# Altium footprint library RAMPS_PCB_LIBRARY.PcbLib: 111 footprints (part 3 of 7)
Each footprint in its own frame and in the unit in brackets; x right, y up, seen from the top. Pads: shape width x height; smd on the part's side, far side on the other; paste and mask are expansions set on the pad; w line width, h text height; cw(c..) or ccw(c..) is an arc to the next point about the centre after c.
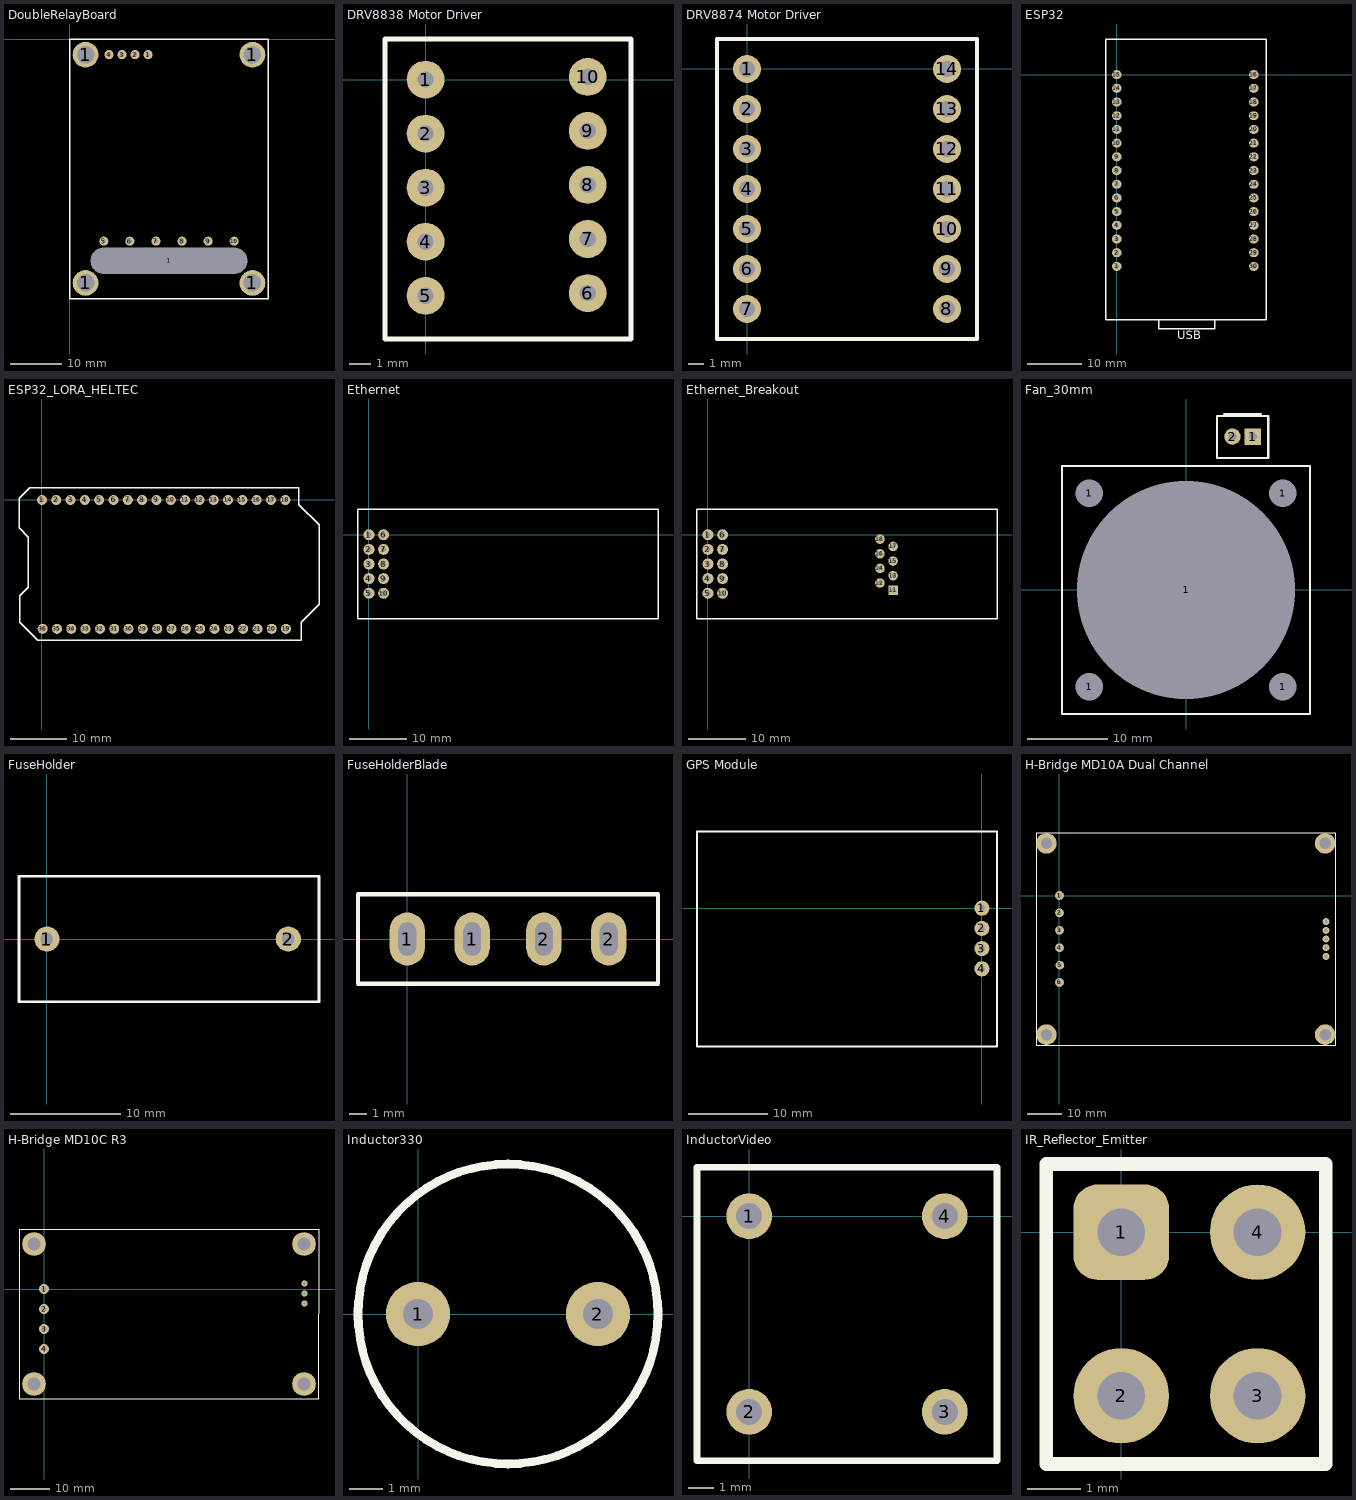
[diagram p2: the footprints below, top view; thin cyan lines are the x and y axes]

## DoubleRelayBoard [mil]
pads (15):
  round 196.85 hole 133.86: 1(120,-1870) 1(120,-120) 1(1400,-1870) 1(1400,-120)
  round 70 hole 30: 1(600,-120) 2(500,-120) 3(400,-120) 4(300,-120) 5(260,-1550) 6(460,-1550) 7(660,-1550) 8(860,-1550) 9(1060,-1550) 10(1260,-1550)
  rect 60x60 hole 200 slot 1200 at 0 deg: 1(760,-1700)
Top Overlay:
  lines w10: 0,-1990 1520,-1990 1520,0 0,0 0,-1990

## DRV8838 Motor Driver [mil]
pads (10):
  round 70 hole 30: 1(0,0) 2(0,-100) 3(0,-200) 4(0,-300) 5(0,-400) 6(300,-395) 7(300,-295) 8(300,-195) 9(300,-95) 10(300,5)
Top Overlay:
  lines w10: -75,-480 -75,75 380,75 380,-480 -75,-480

## DRV8874 Motor Driver [mil]
pads (14):
  round 70 hole 40: 1(0,0) 2(0,-100) 3(0,-200) 4(0,-300) 5(0,-400) 6(0,-500) 7(0,-600) 8(500,-600) 9(500,-500) 10(500,-400) 11(500,-300) 12(500,-200) 13(500,-100) 14(500,0)
Top Overlay:
  lines w10: -75,-675 -75,75 575,75 575,-675 -75,-675

## ESP32 [mil]
pads (30):
  oval 70x65 hole 35: 1(0,-1400) 2(0,-1300) 3(0,-1200) 4(0,-1100) 5(0,-1000) 6(0,-900) 7(0,-800) 8(0,-700) 9(0,-600) 10(0,-500) 11(0,-400) 12(0,-300) 13(0,-200) 14(0,-100) 15(0,0) 16(1000,0) 17(1000,-100) 18(1000,-200) 19(1000,-300) 20(1000,-400) 21(1000,-500) 22(1000,-600) 23(1000,-700) 24(1000,-800) 25(1000,-900) 26(1000,-1000) 27(1000,-1100) 28(1000,-1200) 29(1000,-1300) 30(1000,-1400)
Top Overlay:
  lines w10: 305,-1795 305,-1855 715,-1855 715,-1790 ; -80,-1790 1090,-1790 1090,260 -80,260 -80,-1790
  text "USB" at 440,-1930 h60

## ESP32_LORA_HELTEC [mil]
pads (36):
  round 70 hole 35: 1(0,0) 2(100,0) 3(200,0) 4(300,0) 5(400,0) 6(500,0) 7(600,0) 8(700,0) 9(800,0) 10(900,0) 11(1000,0) 12(1100,0) 13(1200,0) 14(1300,0) 15(1400,0) 16(1500,0) 17(1600,0) 18(1700,0) 19(1705,-900) 20(1605,-900) 21(1505,-900) 22(1405,-900) 23(1305,-900) 24(1205,-900) 25(1105,-900) 26(1005,-900) 27(905,-900) 28(805,-900) 29(705,-900) 30(605,-900) 31(505,-900) 32(405,-900) 33(305,-900) 34(205,-900) 35(105,-900) 36(5,-900)
Top Overlay:
  lines w10: -160,-195 -160,10 -85,85 -75,85 1795,85 1795,-35 1935,-175 1935,-730 1810,-855 1810,-980 -30,-980 -155,-855 -155,-670 -95,-610 -95,-260 -160,-195

## Ethernet [mil]
pads (10):
  round 75 hole 35: 1(0,0) 2(0,-100) 3(0,-200) 4(0,-300) 5(0,-400) 6(100,0) 7(100,-100) 8(100,-200) 9(100,-300) 10(100,-400)
Top Overlay:
  lines w10: -75,-575 -75,175 1975,175 1975,-575 -75,-575

## Ethernet_Breakout [mil]
pads (18):
  round 75 hole 35: 1(0,0) 2(0,-100) 3(0,-200) 4(0,-300) 5(0,-400) 6(100,0) 7(100,-100) 8(100,-200) 9(100,-300) 10(100,-400)
  rect 65x65 hole 30: 11(1265,-380)
  round 65 hole 30: 12(1175,-330) 13(1265,-280) 14(1175,-230) 15(1265,-180) 16(1175,-130) 17(1265,-80) 18(1175,-30)
Top Overlay:
  lines w10: -75,-575 1975,-575 1975,175 -75,175 -75,-575

## Fan_30mm [mil]
pads (7):
  round 60 hole 133.86: 1(-472.44,-472.44) 1(-472.44,472.44) 1(472.44,-472.44) 1(472.44,472.44)
  round 60 hole 1062.99: 1(0,0)
  rect 80x80 hole 40: 1(326.23,748.05)
  round 80 hole 40: 2(226.23,748.05)
Top Overlay:
  lines w10: 186.23,858.05 366.23,858.05 ; -605,-605 605,-605 605,605 -605,605 -605,-605 ; 151.23,643.05 151.23,848.05 401.23,848.05 401.23,643.05 151.23,643.05

## FuseHolder [mil]
pads (2):
  round 90 hole 45: 1(0,0) 2(865,0)
Top Overlay:
  lines w10: -100,-225 -100,225 975,225 975,-225 -100,-225

## FuseHolderBlade [mm]
pads (4):
  oval 2x3 hole 1 slot 1.9 at 90 deg: 1(0,0) 1(3.683,0) 2(7.747,0) 2(11.43,0)
Top Overlay:
  lines w0.254: -2.794,-2.54 -2.794,2.54 14.224,2.54 14.224,-2.54 -2.794,-2.54

## GPS Module [mil]
pads (4):
  round 75 hole 30: 1(0,0) 2(0,-100) 3(0,-200) 4(0,-300)
Top Overlay:
  lines w10: -1410,-685 -1410,380 75,380 75,-685 -1410,-685

## H-Bridge MD10A Dual Channel [mil]
pads (15):
  round 100 hole 50: 1(0,0) 2(0,-200) 3(0,-400) 4(0,-600) 5(5,-800) 6(0,-1000)
  round 80 hole 40: 7(3065,-700) 8(3065,-600) 9(3065,-500) 10(3065,-400) 11(3065,-300)
  round 236.22 hole 129.92: ""(-150,-1600) ""(-150,600) ""(3055,-1600) ""(3055,600)
Top Overlay:
  lines w10: -270,-1720 -270,720 3180,720 3180,-1720 -270,-1720

## H-Bridge MD10C R3 [mil]
pads (11):
  round 100 hole 50: 1(0,0) 2(0,-200) 3(0,-400) 4(0,-600)
  round 60 hole 30: 5(2605,-145) 6(2605,-45) 7(2605,55)
  round 236.22 hole 129.92: ""(-100,-950) ""(-100,450) ""(2600,-950) ""(2600,450)
Top Overlay:
  lines w10: -250,-1100 -250,600 2750,600 2750,-1100 -250,-1100

## Inductor330 [mil]
pads (2):
  round 75 hole 35: 1(0,0) 2(210,0)
Top Overlay:
  circle w10: c105,0 r175.07

## InductorVideo [mil]
pads (4):
  round 70 hole 40: 1(0,0) 2(0,-300) 3(300,-300) 4(300,0)
Top Overlay:
  lines w10: -80,-375 -80,75 380,75 380,-375 -80,-375

## IR_Reflector_Emitter [mil]
pads (4):
  rrect50% 70x70 hole 35: 1(0,0)
  round 70 hole 35: 2(0,-120) 3(100,-120) 4(100,0)
Top Overlay:
  lines w10: -55,-170 -55,50 150,50 150,-100 150,-170 -55,-170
